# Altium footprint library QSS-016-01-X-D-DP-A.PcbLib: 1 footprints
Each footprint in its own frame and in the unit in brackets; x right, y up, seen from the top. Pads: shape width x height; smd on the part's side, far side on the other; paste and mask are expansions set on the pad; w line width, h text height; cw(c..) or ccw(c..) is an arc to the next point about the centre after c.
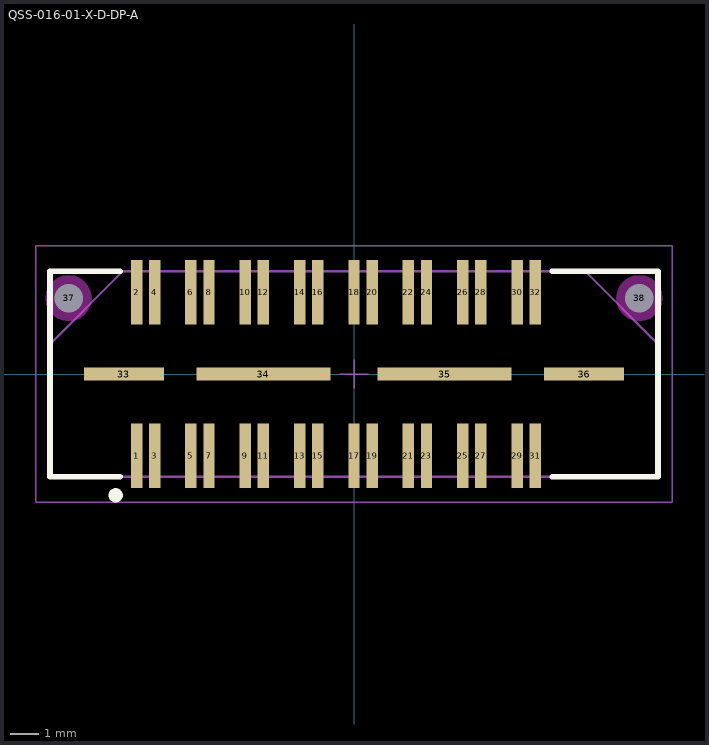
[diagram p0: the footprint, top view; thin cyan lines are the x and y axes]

## QSS-016-01-X-D-DP-A [mm] "0.635mm pitch, 32 pin, high speed socket; differential"
height 3.43
pads (38):
  rect 0.4x2.25 smd mask+0: 1(-7.62,-2.865) 2(-7.62,2.865) 3(-6.985,-2.865) 4(-6.985,2.865) 5(-5.715,-2.865) 6(-5.715,2.865) 7(-5.08,-2.865) 8(-5.08,2.865) 9(-3.81,-2.865) 10(-3.81,2.865) 11(-3.175,-2.865) 12(-3.175,2.865) 13(-1.905,-2.865) 14(-1.905,2.865) 15(-1.27,-2.865) 16(-1.27,2.865) 17(0,-2.865) 18(0,2.865) 19(0.635,-2.865) 20(0.635,2.865) 21(1.905,-2.865) 22(1.905,2.865) 23(2.54,-2.865) 24(2.54,2.865) 25(3.81,-2.865) 26(3.81,2.865) 27(4.445,-2.865) 28(4.445,2.865) 29(5.715,-2.865) 30(5.715,2.865) 31(6.35,-2.865) 32(6.35,2.865)
  rect 2.8x0.45 smd mask+0: 33(-8.064,0) 36(8.064,0)
  rect 4.7x0.45 smd mask+0: 34(-3.175,0) 35(3.175,0)
  round 0.5 hole 1 unplated mask+0: 37(-10.003,2.657) 38(10,2.657)
Top Overlay:
  circle w0.25: c-8.35,-4.25 r0.125
  lines w0.2: -8.2,-3.6 -10.65,-3.6 -10.65,3.6 -8.2,3.6 ; 6.95,-3.6 10.65,-3.6 10.65,3.6 6.95,3.6
Keep-Out Layer:
  pour cut-out: 10.807,2.657 10.779,2.866 10.699,3.06 10.571,3.228 10.403,3.356 10.209,3.436 10,3.464 9.791,3.436 9.597,3.356 9.429,3.228 9.301,3.06 9.221,2.866 9.193,2.657 9.221,2.448 9.301,2.254 9.429,2.086 9.597,1.958 9.791,1.878 10,1.85 10.209,1.878 10.403,1.958 10.571,2.086 10.699,2.254 10.779,2.448
  pour cut-out: -9.196,2.657 -9.224,2.866 -9.304,3.06 -9.432,3.228 -9.6,3.356 -9.794,3.436 -10.003,3.464 -10.212,3.436 -10.406,3.356 -10.574,3.228 -10.702,3.06 -10.782,2.866 -10.81,2.657 -10.782,2.448 -10.702,2.254 -10.574,2.086 -10.406,1.958 -10.212,1.878 -10.003,1.85 -9.794,1.878 -9.6,1.958 -9.432,2.086 -9.304,2.254 -9.224,2.448
Mechanical 12:
  lines w0.001: -10.65,-3.6 -10.65,3.6 10.65,3.6 10.65,-3.6 -10.65,-3.6
Mechanical 13:
  lines w0.076: -10.65,1.05 -8.1,3.6 ; 8.1,3.6 10.65,1.05
  lines w0.1: -10.65,-3.6 -10.65,3.6 10.65,3.6 10.65,-3.6 -10.65,-3.6
  text ".Designator" at 0,0 h1.52
Mechanical 15:
  lines w0.05: -0.5,0 0.5,0 ; 0,-0.5 0,0.5 ; -11.15,-4.5 -11.15,4.5 11.15,4.5 11.15,-4.5 -11.15,-4.5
